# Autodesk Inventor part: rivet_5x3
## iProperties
Created: 2011-01
Part Number: rivet_5x3
Document SubType Name: Modeling
Designer: eric
Density: 1 g/cm^3
Mass: 0.11133 g
Surface Area: 2.1114 cm^2
Volume: 0.11133 cm^3
Author: eric
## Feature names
1. Base1
